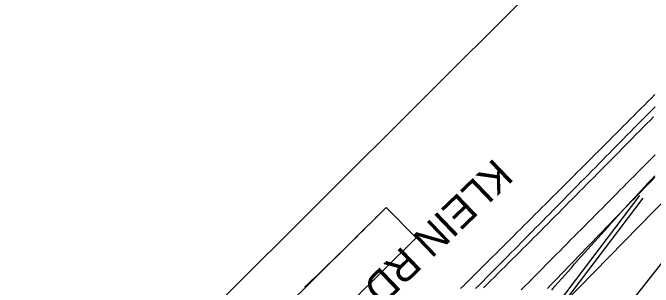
# Model space of a CAD drawing. Extents: x 2252205 to 2259955, y 13788514 to 13798103.
# Drawn here: x 2256389.3 to 2256517.5, y 13792347 to 13792401.9 of the extents above; entities that cross this region are included whole.
import ezdxf

# ---------------------------------------------------------------- set-up
doc = ezdxf.new("R2010")
doc.units = 0
for name, color, linetype in [('D_RDWY_TRACK_BUS', 7, 'Continuous'), ('D_RDWY_TRACK_TRUCK_WB62', 7, 'Continuous'), ('GEOM_CENTERLINE_ALIGN', 7, 'Continuous'), ('Road_Curb_Back', 7, 'Continuous'), ('Road_Curb_Face', 7, 'Continuous'), ('Road_EdgeOfPavementOutside', 7, 'Continuous'), ('ROAD_LABEL_ROADWAYS', 7, 'Continuous'), ('ROAD_ROW_EXIST', 7, 'Continuous'), ('ROAD_ROW_PROPOSED', 7, 'Continuous')]:
    doc.layers.add(name, color=color, linetype=linetype)

msp = doc.modelspace()

# ---------------------------------------------------------------- linework, layer by layer
at = {"layer": 'D_RDWY_TRACK_BUS'}
for points in [[(2256478.95, 13792346.76), (2256479.66, 13792347.46), (2256480.37, 13792348.16), (2256481.08, 13792348.87), (2256481.79, 13792349.57), (2256482.49, 13792350.27), (2256483.2, 13792350.98), (2256483.91, 13792351.68), (2256484.62, 13792352.39), (2256485.33, 13792353.09), (2256486.04, 13792353.79), (2256486.75, 13792354.5), (2256487.45, 13792355.2), (2256488.16, 13792355.91), (2256488.87, 13792356.61), (2256489.58, 13792357.32), (2256490.29, 13792358.03), (2256490.99, 13792358.73), (2256491.7, 13792359.44), (2256492.41, 13792360.14), (2256493.12, 13792360.85), (2256493.83, 13792361.55), (2256494.53, 13792362.26), (2256495.24, 13792362.97), (2256495.95, 13792363.67), (2256496.65, 13792364.38), (2256497.36, 13792365.09), (2256498.07, 13792365.79), (2256498.78, 13792366.5), (2256499.48, 13792367.21), (2256500.19, 13792367.91), (2256500.9, 13792368.62), (2256501.6, 13792369.33), (2256502.31, 13792370.03), (2256503.02, 13792370.74), (2256503.72, 13792371.45), (2256504.43, 13792372.15), (2256505.14, 13792372.86), (2256505.84, 13792373.57), (2256506.55, 13792374.28), (2256507.26, 13792374.98), (2256507.96, 13792375.69), (2256508.67, 13792376.4), (2256509.38, 13792377.1), (2256510.08, 13792377.81), (2256510.79, 13792378.52), (2256511.5, 13792379.23), (2256512.2, 13792379.93), (2256512.91, 13792380.64), (2256513.61, 13792381.35), (2256514.32, 13792382.06), (2256515.03, 13792382.77), (2256515.73, 13792383.47), (2256516.44, 13792384.18), (2256517.15, 13792384.89), (2256517.85, 13792385.6)], [(2256491.1, 13792346.51), (2256491.8, 13792347.22), (2256492.51, 13792347.93), (2256493.21, 13792348.65), (2256493.92, 13792349.36), (2256494.62, 13792350.07), (2256495.33, 13792350.78), (2256496.03, 13792351.5), (2256496.74, 13792352.21), (2256497.44, 13792352.92), (2256498.15, 13792353.63), (2256498.85, 13792354.34), (2256499.56, 13792355.06), (2256500.26, 13792355.77), (2256500.97, 13792356.48), (2256501.67, 13792357.19), (2256502.38, 13792357.9), (2256503.08, 13792358.61), (2256503.79, 13792359.32), (2256504.49, 13792360.03), (2256505.2, 13792360.74), (2256505.9, 13792361.46), (2256506.61, 13792362.17), (2256507.32, 13792362.88), (2256508.02, 13792363.59), (2256508.73, 13792364.3), (2256509.43, 13792365.01), (2256510.14, 13792365.72), (2256510.84, 13792366.43), (2256511.55, 13792367.14), (2256512.25, 13792367.85), (2256512.96, 13792368.56), (2256513.66, 13792369.27), (2256514.37, 13792369.98), (2256515.07, 13792370.69), (2256515.78, 13792371.4), (2256516.49, 13792372.11), (2256517.19, 13792372.82), (2256517.9, 13792373.53)]]:
    msp.add_lwpolyline(points, dxfattribs=at)
at = {"layer": 'D_RDWY_TRACK_TRUCK_WB62'}
for points in [[(2256481.96, 13792346.76), (2256482.67, 13792347.47), (2256483.37, 13792348.18), (2256484.08, 13792348.9), (2256484.79, 13792349.61), (2256485.5, 13792350.33), (2256486.21, 13792351.04), (2256486.91, 13792351.75), (2256487.62, 13792352.47), (2256488.32, 13792353.18), (2256489.03, 13792353.89), (2256489.74, 13792354.61), (2256490.44, 13792355.32), (2256491.15, 13792356.04), (2256491.85, 13792356.75), (2256492.56, 13792357.46), (2256493.26, 13792358.18), (2256493.97, 13792358.89), (2256494.67, 13792359.6), (2256495.38, 13792360.32), (2256496.08, 13792361.03), (2256496.78, 13792361.74), (2256497.49, 13792362.46), (2256498.19, 13792363.17), (2256498.9, 13792363.88), (2256499.6, 13792364.6), (2256500.3, 13792365.31), (2256501.01, 13792366.02), (2256501.71, 13792366.74), (2256502.41, 13792367.45), (2256503.11, 13792368.16), (2256503.82, 13792368.88), (2256504.52, 13792369.59), (2256505.22, 13792370.31), (2256505.93, 13792371.02), (2256506.63, 13792371.73), (2256507.33, 13792372.45), (2256508.03, 13792373.16), (2256508.73, 13792373.87), (2256509.44, 13792374.59), (2256510.14, 13792375.3), (2256510.84, 13792376.01), (2256511.54, 13792376.73), (2256512.25, 13792377.44), (2256512.95, 13792378.15), (2256513.65, 13792378.87), (2256514.35, 13792379.58), (2256515.05, 13792380.29), (2256515.75, 13792381.01), (2256516.46, 13792381.72), (2256517.16, 13792382.43), (2256517.86, 13792383.15)], [(2256497.19, 13792346.46), (2256497.84, 13792347.21), (2256498.49, 13792347.95), (2256499.15, 13792348.7), (2256499.8, 13792349.45), (2256500.46, 13792350.19), (2256501.12, 13792350.93), (2256501.78, 13792351.68), (2256502.44, 13792352.42), (2256503.1, 13792353.16), (2256503.76, 13792353.9), (2256504.42, 13792354.65), (2256505.09, 13792355.39), (2256505.75, 13792356.13), (2256506.42, 13792356.86), (2256507.08, 13792357.6), (2256507.75, 13792358.34), (2256508.42, 13792359.08), (2256509.09, 13792359.82), (2256509.76, 13792360.55), (2256510.43, 13792361.29), (2256511.1, 13792362.02), (2256511.77, 13792362.76), (2256512.44, 13792363.49), (2256513.11, 13792364.23), (2256513.79, 13792364.96), (2256514.46, 13792365.69), (2256515.14, 13792366.42), (2256515.81, 13792367.16), (2256516.49, 13792367.89), (2256517.17, 13792368.62), (2256517.85, 13792369.35)], [(2256424.2, 13792311.55), (2256421.36, 13792308.73), (2256415.38, 13792314.77), (2256464.05, 13792362.98), (2256470.03, 13792356.94), (2256424.2, 13792311.55)], [(2256462.27, 13792361.22), (2256461.56, 13792360.51), (2256460.85, 13792359.81), (2256460.14, 13792359.11), (2256459.43, 13792358.41), (2256458.73, 13792357.71), (2256458.02, 13792357.01), (2256457.32, 13792356.32), (2256456.62, 13792355.62), (2256455.92, 13792354.93), (2256455.22, 13792354.25), (2256454.53, 13792353.57), (2256453.84, 13792352.89), (2256453.15, 13792352.22), (2256452.46, 13792351.55), (2256451.77, 13792350.88), (2256451.09, 13792350.22), (2256450.41, 13792349.57), (2256449.73, 13792348.92), (2256449.05, 13792348.28), (2256448.38, 13792347.64), (2256447.71, 13792347.01)]]:
    msp.add_lwpolyline(points, dxfattribs=at)
at = {"layer": 'GEOM_CENTERLINE_ALIGN'}
msp.add_arc((2265119, 13799669.27), 11459.16, 219.418553, 224.327385, dxfattribs=at)
at = {"layer": 'Road_Curb_Back'}
msp.add_line((2256463.07, 13792295.92), (2256515.49, 13792364.86), dxfattribs=at)
at = {"layer": 'Road_Curb_Face'}
for points in [[(2256483.56, 13792346.92), (2256484.28, 13792347.63), (2256485, 13792348.34), (2256485.71, 13792349.05), (2256486.43, 13792349.77), (2256487.14, 13792350.48), (2256487.86, 13792351.19), (2256488.57, 13792351.9), (2256489.29, 13792352.62), (2256490, 13792353.33), (2256490.71, 13792354.04), (2256491.42, 13792354.75), (2256492.13, 13792355.47), (2256492.85, 13792356.18), (2256493.56, 13792356.89), (2256494.27, 13792357.6), (2256494.98, 13792358.32), (2256495.69, 13792359.03), (2256496.4, 13792359.74), (2256497.1, 13792360.46), (2256497.81, 13792361.17), (2256498.52, 13792361.88), (2256499.23, 13792362.59), (2256499.94, 13792363.31), (2256500.64, 13792364.02), (2256501.35, 13792364.73), (2256502.06, 13792365.45), (2256502.77, 13792366.16), (2256503.47, 13792366.87), (2256504.18, 13792367.58), (2256504.88, 13792368.3), (2256505.59, 13792369.01), (2256506.3, 13792369.72), (2256507, 13792370.44), (2256507.71, 13792371.15), (2256508.41, 13792371.86), (2256509.12, 13792372.58), (2256509.82, 13792373.29), (2256510.52, 13792374), (2256511.23, 13792374.72), (2256511.93, 13792375.43), (2256512.64, 13792376.14), (2256513.34, 13792376.86), (2256514.04, 13792377.57), (2256514.75, 13792378.28), (2256515.45, 13792379), (2256516.16, 13792379.71), (2256516.86, 13792380.42), (2256517.56, 13792381.14)], [(2256496.35, 13792346.76), (2256497.04, 13792347.49), (2256497.73, 13792348.21), (2256498.42, 13792348.93), (2256499.11, 13792349.65), (2256499.8, 13792350.37), (2256500.49, 13792351.09), (2256501.18, 13792351.81), (2256501.87, 13792352.53), (2256502.56, 13792353.25), (2256503.25, 13792353.97), (2256503.95, 13792354.69), (2256504.64, 13792355.41), (2256505.33, 13792356.13), (2256506.03, 13792356.84), (2256506.72, 13792357.56), (2256507.41, 13792358.28), (2256508.11, 13792359), (2256508.8, 13792359.72), (2256509.5, 13792360.44), (2256510.19, 13792361.15), (2256510.89, 13792361.87), (2256511.58, 13792362.59), (2256512.28, 13792363.31), (2256512.97, 13792364.02), (2256513.67, 13792364.74), (2256514.36, 13792365.46), (2256515.06, 13792366.17), (2256515.76, 13792366.89), (2256516.45, 13792367.61), (2256517.15, 13792368.32), (2256517.85, 13792369.04)]]:
    msp.add_lwpolyline(points, dxfattribs=at)
at = {"layer": 'Road_EdgeOfPavementOutside'}
msp.add_line((2256462.4, 13792296.42), (2256514.83, 13792365.36), dxfattribs=at)
at = {"layer": 'ROAD_ROW_EXIST'}
for p, q in [((2256820.78, 13792672.59), (2256436.44, 13792279.21)), ((2256564.59, 13792477.66), (2256403.35, 13792316.84))]:
    msp.add_line(p, q, dxfattribs=at)
at = {"layer": 'ROAD_ROW_PROPOSED'}
msp.add_line((2256569.79, 13792415.7), (2256485.05, 13792308.89), dxfattribs=at)

# ---------------------------------------------------------------- texts
at = {"layer": 'ROAD_LABEL_ROADWAYS'}
msp.add_text('KLEIN RD', height=6, rotation=223.8406, dxfattribs=at).set_placement((2256485.72, 13792373.04))

doc.saveas('drawing.dxf')
